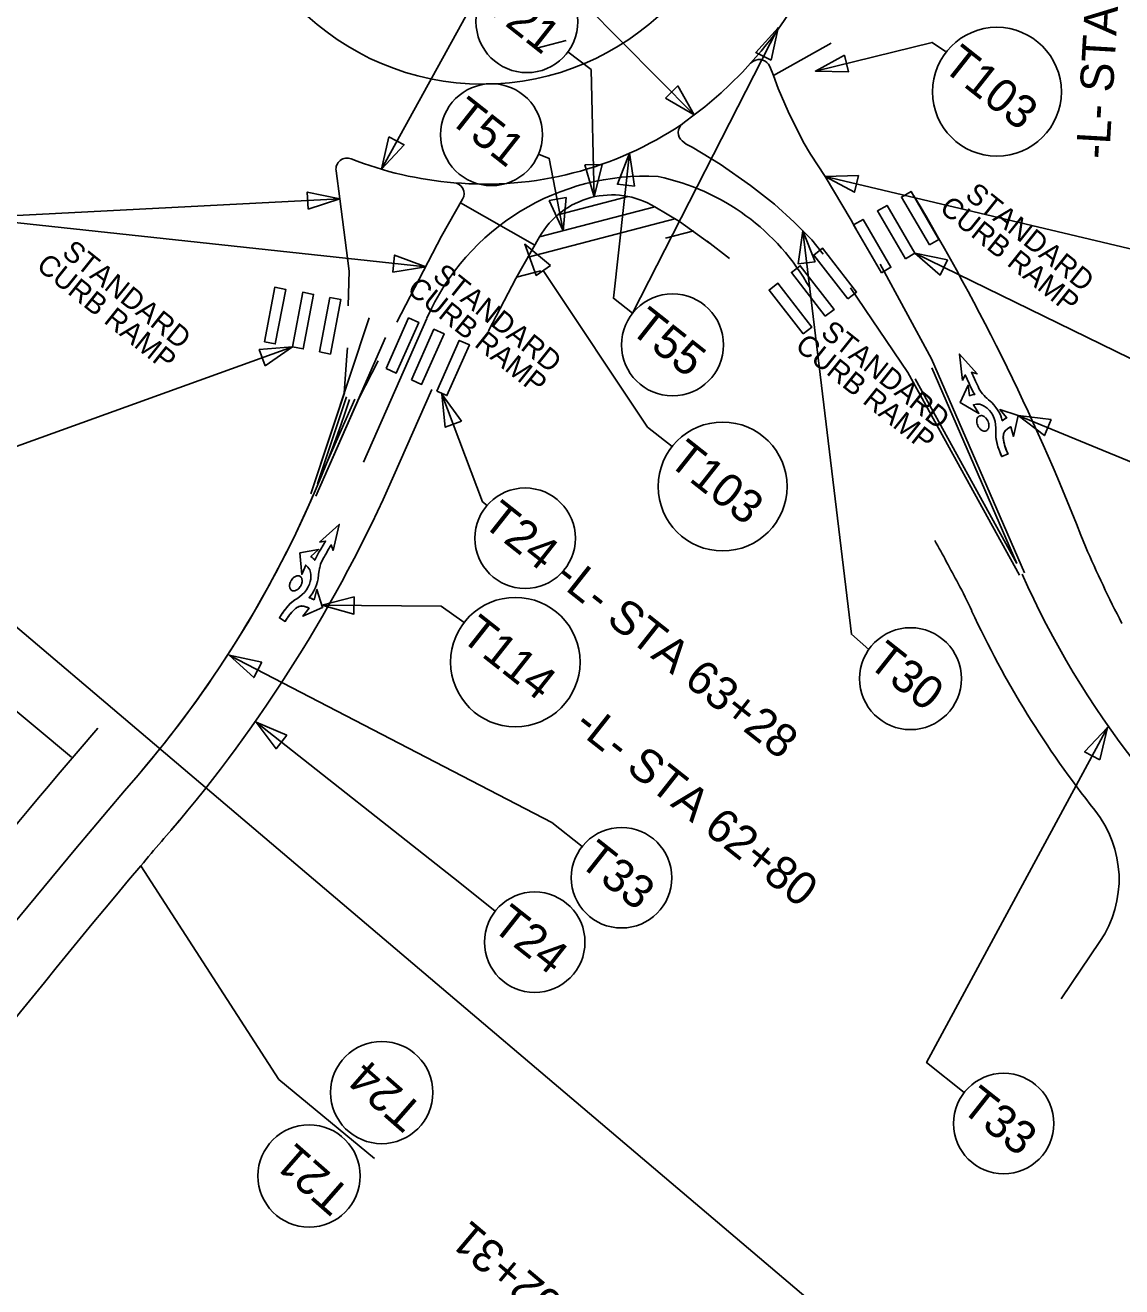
# Model space of a CAD drawing. Extents: x 553958 to 562499, y 493978 to 516388.
# Drawn here: x 557610 to 557807.8, y 506659.2 to 506886.7 of the extents above; entities that cross this region are included whole.
import ezdxf

# ---------------------------------------------------------------- set-up
doc = ezdxf.new("R2010")
doc.units = 0
for name, color, linetype in [('Default', 7, 'Continuous'), ('Exist Horizontal Alignment', 7, 'Continuous'), ('Prop Approach Slab', 7, 'Continuous'), ('Prop Conc 4in Sidewalk', 7, 'Continuous'), ('Prop Conc Curb and Gutter', 7, 'Continuous'), ('Prop EOT', 7, 'Continuous'), ('Prop EOT Dash', 7, 'Continuous'), ('Prop Erosion Rip Rap Class II Label', 7, 'Continuous'), ('Prop Horizontal Alignment Tick Label', 7, 'Continuous'), ('Prop SS Cut Line', 7, 'Continuous'), ('Prop SS Fill Line', 7, 'Continuous'), ('Raster_Level_0', 7, 'Continuous'), ('Scratch_Level_4', 7, 'Continuous'), ('Sheet Plan CELL', 7, 'Continuous'), ('Sheet Plot Border Inside CELL', 7, 'Continuous'), ('Sheet Plot Border Outside CELL', 7, 'Continuous')]:
    doc.layers.add(name, color=color, linetype=linetype)

msp = doc.modelspace()

# ---------------------------------------------------------------- linework, layer by layer
at = {"layer": 'Default'}
msp.add_arc((557478.54, 506881.64), 200, 319.3989, 341.8064, dxfattribs=at)
at = {"layer": 'Exist Horizontal Alignment'}
msp.add_circle((557692.58, 506923.08), 47, dxfattribs=at)
at = {"layer": 'Prop Approach Slab'}
for p, q in [((557618.37, 506754.68), (557488.54, 506863.27)), ((557619.58, 506755.76), (557623.14, 506759.92)), ((557623.01, 506759.77), (557623.02, 506759.77)), ((557630.89, 506735.12), (557655.77, 506696.56)), ((557655.77, 506696.56), (557673.04, 506682.35))]:
    msp.add_line(p, q, dxfattribs=at)
msp.add_lwpolyline([(557687.87, 506911.55), (557697.91, 506903.62), (557730.67, 506870.51)], dxfattribs=at)
msp.add_lwpolyline([(557725.49, 506873.54), (557730.67, 506870.51), (557727.69, 506875.73)], close=True, dxfattribs=at)
for centre in [(557700.51, 506887.33), (557694.12, 506866.95)]:
    msp.add_circle(centre, 9.19, dxfattribs=at)
at = {"layer": 'Prop Conc Curb and Gutter'}
msp.add_line((557671.03, 506807.9), (557682.47, 506833.83), dxfattribs=at)
for centre, radius, start, end in [((557721.81, 506816.48), 43, 86.8578, 156.1909), ((557715.73, 506819.23), 41.05, 29.3788, 78.1467)]:
    msp.add_arc(centre, radius, start, end, dxfattribs=at)
at = {"layer": 'Prop EOT'}
msp.add_line((557676.52, 506805.48), (557683.37, 506821), dxfattribs=at)
for centre, radius, start, end in [((557437.73, 506910.84), 261, 319.5426, 336.1909), ((558769.28, 505775.3), 1511, 139.54257, 142.88486), ((558771.28, 505774.06), 1491.35, 139.437, 139.87766)]:
    msp.add_arc(centre, radius, start, end, dxfattribs=at)
at = {"layer": 'Prop EOT Dash'}
for p, q in [((557661.53, 506802.16), (557672.09, 506833.93)), ((557662.44, 506801.76), (557675.01, 506830.38)), ((557790.23, 506787.92), (557773.46, 506826.53)), ((557789.33, 506787.5), (557769.19, 506824.07))]:
    msp.add_line(p, q, dxfattribs=at)
at = {"layer": 'Prop Erosion Rip Rap Class II Label'}
for points in [[(557425.46, 506933.59), (557889.73, 506539.36), (558124.72, 506519.69), (558557.87, 506177.2), (558959.56, 506684.21), (558454.57, 507154), (558185.43, 507366.81), (557535.46, 507286.55), (557335.3, 506986.11)], [(557510.24, 505740.54), (557854.59, 506431.05), (557889.73, 506539.36), (557425.46, 506933.59), (557046.6, 506628.46), (556899.98, 506318.25), (557006.57, 505850.3)]]:
    msp.add_lwpolyline(points, close=True, dxfattribs=at)
at = {"layer": 'Prop Horizontal Alignment Tick Label'}
msp.add_line((557796.84, 506711.13), (557800.95, 506717.2), dxfattribs=at)
at = {"layer": 'Prop SS Cut Line'}
for centre, radius, start, end in [((557692.71, 506924.09), 65.36, 317.419, 337.4894), ((557692.97, 506921.74), 63.7, 264.9256, 303.9381)]:
    msp.add_arc(centre, radius, start, end, dxfattribs=at)
at = {"layer": 'Prop SS Fill Line'}
for p, q in [((557739.39, 506878.24), (557740.84, 506879.87)), ((557741.38, 506880.2), (557740.84, 506879.87)), ((557737.04, 506875.94), (557739.39, 506878.24)), ((557735.56, 506874.52), (557737.04, 506875.94)), ((557732.61, 506872), (557734.29, 506873.39)), ((557735.56, 506874.52), (557734.29, 506873.39)), ((557728.94, 506869.23), (557730.67, 506870.51)), ((557732.61, 506872), (557730.67, 506870.51)), ((557728.94, 506869.23), (557728.53, 506868.89)), ((557803.83, 506721.46), (557796.84, 506711.13))]:
    msp.add_line(p, q, dxfattribs=at)
for centre, radius, start, end in [((557742.43, 506878.5), 2, 22.2051, 121.6618), ((557729.8, 506867.35), 2, 129.4317, 230.0864), ((557668.07, 506860.73), 2, 68.5384, 187.5292), ((557692.58, 506923.08), 65, 248.5384, 265.3704), ((557687.18, 506856.3), 2, 330.2849, 85.3704), ((557413.43, 506642.2), 415.96, 21.2102, 30.9181), ((557398.44, 506584.5), 429.97, 27.9477, 29.122), ((558043.01, 506898.58), 263.97, 203.6499, 206.9793), ((557689.93, 506739.15), 100, 24.8121, 27.9477), ((557940.45, 506854.97), 176, 204.8121, 218.6034), ((557787.28, 506732.68), 20, 325.8636, 38.6034)]:
    msp.add_arc(centre, radius, start, end, dxfattribs=at)
at = {"layer": 'Raster_Level_0'}
msp.add_line((557627.95, 506748.62), (557630.39, 506751.48), dxfattribs=at)
for centre, radius, start, end in [((557478.54, 506881.64), 200, 319.3989, 336.5223), ((557940.45, 506854.97), 165, 204.0535, 231.806), ((558769.28, 505775.3), 1500, 139.54257, 161.63616)]:
    msp.add_arc(centre, radius, start, end, dxfattribs=at)
at = {"layer": 'Scratch_Level_4'}
for points in [[(557773.07, 506847.07), (557768.03, 506855.71), (557769.76, 506856.71), (557774.8, 506848.07)], [(557768.75, 506844.55), (557763.71, 506853.19), (557765.44, 506854.2), (557770.47, 506845.56)], [(557764.43, 506842.03), (557759.39, 506850.67), (557761.12, 506851.68), (557766.15, 506843.04)], [(557758.36, 506837.34), (557752.24, 506845.25), (557753.82, 506846.48), (557759.94, 506838.57)], [(557754.31, 506834.2), (557748.2, 506842.11), (557749.78, 506843.33), (557755.9, 506835.42)], [(557653.17, 506829.6), (557655.04, 506839.43), (557657.01, 506839.05), (557655.14, 506829.23)], [(557750.3, 506831.02), (557744.18, 506838.93), (557745.76, 506840.16), (557751.88, 506832.25)], [(557658.21, 506828.7), (557660.08, 506838.53), (557662.04, 506838.15), (557660.18, 506828.33)], [(557663.13, 506827.77), (557664.99, 506837.59), (557666.96, 506837.22), (557665.09, 506827.39)], [(557675.11, 506824.76), (557679.17, 506833.9), (557680.99, 506833.09), (557676.94, 506823.95)], [(557679.68, 506822.74), (557683.74, 506831.87), (557685.56, 506831.06), (557681.5, 506821.92)], [(557684.25, 506820.71), (557688.31, 506829.85), (557690.13, 506829.03), (557686.07, 506819.89)]]:
    msp.add_lwpolyline(points, close=True, dxfattribs=at)
at = {"layer": 'Sheet Plan CELL'}
for points in [[(557687.87, 506911.55), (557697.91, 506903.62), (557674.29, 506860.71)], [(557719.55, 506834.74), (557745.8, 506886.22)], [(557707.91, 506881.89), (557712.12, 506878.7), (557712.62, 506855.75)], [(557775.97, 506881.92), (557773.55, 506883.6), (557752.52, 506878.41)], [(557702.61, 506863.41), (557704.54, 506862.66), (557707.03, 506849.63)], [(557719.55, 506834.74), (557716.11, 506837.47), (557719.01, 506863.61)], [(557824.48, 506838.7), (557815.88, 506844.83), (557754.27, 506859.43)], [(557593.34, 506857.45), (557600.29, 506851.96), (557666.76, 506855.36)], [(557593.34, 506857.45), (557600.29, 506851.96), (557682.25, 506843.15)], [(557762.14, 506774.14), (557759.01, 506776.86), (557750.28, 506849.59)], [(557834.46, 506812.15), (557827.3, 506817.81), (557770.47, 506845.56)], [(557726.68, 506810.72), (557722.27, 506814.21), (557703.46, 506842.47)], [(557590.14, 506810.92), (557596.04, 506806.25), (557658.21, 506828.7)], [(557693.32, 506800.11), (557692.52, 506800.77), (557685.18, 506820.15)], [(557864.74, 506781.88), (557856.09, 506788.72), (557789.06, 506816.34)], [(557689.19, 506779), (557685.03, 506781.95), (557663.53, 506782.09)], [(557710.46, 506738.58), (557705.01, 506742.9), (557646.83, 506773.11)], [(557694.8, 506726.96), (557688.39, 506732.03), (557651.69, 506761.04)], [(557779.37, 506694.26), (557772.56, 506699.64), (557805.18, 506760.06)]]:
    msp.add_lwpolyline(points, dxfattribs=at)
for points in [[(557744.52, 506880.36), (557745.8, 506886.22), (557741.76, 506881.79)], [(557757.78, 506881.3), (557752.52, 506878.41), (557758.52, 506878.29)], [(557675.6, 506866.56), (557674.29, 506860.71), (557678.35, 506865.12)], [(557710.95, 506861.51), (557712.62, 506855.75), (557714.05, 506861.57)], [(557719.92, 506857.68), (557719.01, 506863.61), (557716.83, 506858.02)], [(557760.27, 506859.61), (557754.27, 506859.43), (557759.55, 506856.58)], [(557661.05, 506853.51), (557666.76, 506855.36), (557660.89, 506856.61)], [(557704.52, 506855.08), (557707.03, 506849.63), (557707.58, 506855.61)], [(557752.51, 506844.02), (557750.28, 506849.59), (557749.43, 506843.65)], [(557704.73, 506843.36), (557700.11, 506847.19), (557702.2, 506841.57)], [(557776.36, 506844.41), (557770.47, 506845.56), (557775, 506841.62)], [(557676.34, 506842.15), (557682.25, 506843.15), (557676.63, 506845.24)], [(557653.29, 506825.27), (557658.21, 506828.7), (557652.24, 506828.19)], [(557688.69, 506815.28), (557685.18, 506820.15), (557685.78, 506814.18)], [(557795.01, 506815.57), (557789.06, 506816.34), (557793.83, 506812.7)], [(557669.34, 506783.61), (557663.53, 506782.09), (557669.32, 506780.5)], [(557652.69, 506771.82), (557646.83, 506773.11), (557651.26, 506769.06)], [(557657.2, 506758.66), (557651.69, 506761.04), (557655.28, 506756.23)], [(557803.79, 506754.22), (557805.18, 506760.06), (557801.06, 506755.69)]]:
    msp.add_lwpolyline(points, close=True, dxfattribs=at)
for centre, radius in [((557785.25, 506874.69), 11.62), ((557726.76, 506829.04), 9.19), ((557735.8, 506803.51), 11.62), ((557700.18, 506794.18), 9.06), ((557698.42, 506771.85), 11.67), ((557769.67, 506768.86), 9.19), ((557717.57, 506732.96), 9.06), ((557701.91, 506721.34), 9.06), ((557674.33, 506694.23), 9.22), ((557786.47, 506688.64), 9.06), ((557661.23, 506679.19), 9.22)]:
    msp.add_circle(centre, radius, dxfattribs=at)
at = {"layer": 'Sheet Plot Border Inside CELL'}
for p, q in [((557702.05, 506882.49), (557707.59, 506883.93)), ((557744.95, 506877.63), (557755.38, 506883.43)), ((557688.55, 506854.67), (557701.93, 506847.02)), ((557718.77, 506855.8), (557706.06, 506852.48)), ((557723.55, 506853.95), (557702.79, 506848.53)), ((557723.55, 506853.95), (557728.01, 506851.27)), ((557727.15, 506851.79), (557700.71, 506844.88)), ((557728.01, 506851.27), (557733.45, 506847.4)), ((557702.79, 506848.53), (557698.51, 506841.02)), ((557730.63, 506849.6), (557725.52, 506848.26)), ((557733.01, 506847.75), (557737.02, 506844.63)), ((557698.51, 506841.02), (557693.59, 506831.57)), ((557703.03, 506842.39), (557698.62, 506841.24))]:
    msp.add_line(p, q, dxfattribs=at)
for points in [[(557779.06, 506822.64), (557778.5, 506827.4), (557781.67, 506823.8), (557780.68, 506824.1), (557781.2, 506822.92), (557781.38, 506822.52), (557781.57, 506822.13), (557781.67, 506821.9), (557781.86, 506821.52), (557782.02, 506821.2), (557782.19, 506820.89), (557782.44, 506820.52), (557782.65, 506820.25), (557782.82, 506820.05), (557782.96, 506819.9), (557783.22, 506819.64), (557783.43, 506819.44), (557783.76, 506819.16), (557784.31, 506818.66), (557784.68, 506818.26), (557785.08, 506817.77), (557785.37, 506817.35), (557785.7, 506816.77), (557785.94, 506816.24), (557786.08, 506815.85), (557786.21, 506815.38), (557786.45, 506815.55), (557786.76, 506815.75), (557787.02, 506815.9), (557785.78, 506817.38), (557789.06, 506816.34), (557788.26, 506812.53), (557787.76, 506814.29), (557787.41, 506814.08), (557787.23, 506813.96), (557787.08, 506813.86), (557786.94, 506813.74), (557786.82, 506813.62), (557786.65, 506813.41), (557786.57, 506813.28), (557786.48, 506813.02), (557786.44, 506812.88), (557786.41, 506812.69), (557786.39, 506812.46), (557786.4, 506812.22), (557786.43, 506812.04), (557786.48, 506811.68), (557786.55, 506811.36), (557786.63, 506811.03), (557786.73, 506810.67), (557786.83, 506810.38), (557786.97, 506810.01), (557787.11, 506809.69), (557787.25, 506809.4), (557786.13, 506808.9), (557785.98, 506809.25), (557785.7, 506809.96), (557785.44, 506810.68), (557785.23, 506811.43), (557785.13, 506811.97), (557785.07, 506812.57), (557785.06, 506813.02), (557785.08, 506813.43), (557785.07, 506814.05), (557785.02, 506814.67), (557784.93, 506815.23), (557784.77, 506815.79), (557784.5, 506816.37), (557784.22, 506816.83), (557783.92, 506817.21), (557783.62, 506817.54), (557783.48, 506817.63), (557782.96, 506818.01), (557782.61, 506818.2), (557782.16, 506818.34), (557781.84, 506818.38), (557781.56, 506818.35), (557781.02, 506818.24), (557782, 506816.69), (557778.63, 506818.63), (557780.04, 506821.77), (557780.31, 506819.87), (557780.6, 506819.98), (557780.84, 506820.04), (557781.12, 506820.08), (557781.25, 506820.08), (557780.98, 506820.54), (557780.71, 506821.05), (557780.49, 506821.51), (557780.23, 506822.09), (557779.53, 506823.64)], [(557663.1, 506793.48), (557666.68, 506796.66), (557665.55, 506792), (557665.23, 506792.98), (557664.56, 506791.88), (557664.34, 506791.5), (557664.12, 506791.13), (557664, 506790.91), (557663.79, 506790.54), (557663.62, 506790.22), (557663.47, 506789.91), (557663.31, 506789.5), (557663.2, 506789.17), (557663.14, 506788.91), (557663.09, 506788.71), (557663.03, 506788.35), (557662.98, 506788.06), (557662.94, 506787.63), (557662.85, 506786.89), (557662.73, 506786.36), (557662.56, 506785.75), (557662.38, 506785.27), (557662.1, 506784.67), (557661.8, 506784.17), (557661.56, 506783.83), (557661.24, 506783.45), (557661.52, 506783.36), (557661.86, 506783.22), (557662.14, 506783.09), (557662.64, 506784.95), (557663.67, 506781.67), (557660.08, 506780.15), (557661.24, 506781.56), (557660.87, 506781.73), (557660.67, 506781.81), (557660.49, 506781.87), (557660.31, 506781.92), (557660.15, 506781.95), (557659.88, 506781.97), (557659.73, 506781.95), (557659.46, 506781.89), (557659.32, 506781.84), (557659.15, 506781.76), (557658.96, 506781.64), (557658.77, 506781.49), (557658.63, 506781.37), (557658.37, 506781.12), (557658.14, 506780.88), (557657.91, 506780.62), (557657.68, 506780.34), (557657.5, 506780.09), (557657.28, 506779.76), (557657.09, 506779.46), (557656.94, 506779.18), (557655.88, 506779.82), (557656.09, 506780.13), (557656.51, 506780.77), (557656.95, 506781.39), (557657.45, 506782), (557657.83, 506782.39), (557658.29, 506782.79), (557658.66, 506783.05), (557659, 506783.27), (557659.51, 506783.63), (557659.99, 506784.03), (557660.39, 506784.42), (557660.75, 506784.87), (557661.08, 506785.43), (557661.3, 506785.92), (557661.44, 506786.38), (557661.54, 506786.82), (557661.53, 506786.98), (557661.54, 506787.63), (557661.5, 506788.02), (557661.36, 506788.48), (557661.2, 506788.75), (557661.02, 506788.97), (557660.62, 506789.35), (557659.91, 506787.66), (557659.57, 506791.53), (557662.95, 506792.17), (557661.55, 506790.86), (557661.81, 506790.69), (557661.99, 506790.52), (557662.18, 506790.32), (557662.26, 506790.22), (557662.49, 506790.7), (557662.75, 506791.21), (557663, 506791.66), (557663.33, 506792.2), (557664.2, 506793.66)]]:
    msp.add_lwpolyline(points, close=True, dxfattribs=at)
for points in [[(557787.76, 506814.29), (557788.26, 506812.53), (557789.06, 506816.34), (557785.78, 506817.38), (557787.02, 506815.9)], [(557786.13, 506808.9), (557787.25, 506809.4)], [(557661.24, 506781.56), (557660.08, 506780.15), (557663.67, 506781.67), (557662.64, 506784.95), (557662.14, 506783.09)], [(557655.88, 506779.82), (557656.94, 506779.18)]]:
    msp.add_lwpolyline(points, dxfattribs=at)
for centre, radius, start, end in [((557715.82, 506841.09), 15, 58.9904, 150.2849), ((557782.44, 506815.53), 0.777, 138.4443, 158.6453), ((557782.42, 506815.56), 0.742, 115.3307, 138.4443), ((557782.36, 506815.67), 0.613, 114.0973, 115.3307), ((557782.36, 506815.67), 0.613, 112.8639, 114.0973), ((557782.41, 506815.55), 0.742, 89.7503, 112.8639), ((557782.41, 506815.52), 0.777, 69.5494, 89.7503), ((557782.19, 506814.94), 1.4, 46.8199, 69.5494), ((557781.78, 506814.49), 2.01, 38.835, 46.8199), ((557789.72, 506810.86), 5.72, 118.1402, 127.8449), ((557783.02, 506815.31), 1.4, 158.6453, 181.3747), ((557783.63, 506815.32), 2.01, 181.3747, 189.3596), ((557783.73, 506815.34), 2.1, 189.3596, 202.0588), ((557783.61, 506815.29), 1.98, 202.0588, 204.0973), ((557783.61, 506815.29), 1.98, 204.0973, 206.1359), ((557783.72, 506815.35), 2.1, 206.1359, 218.835), ((557783.65, 506815.29), 2.01, 218.835, 226.8199), ((557783.23, 506814.84), 1.4, 226.8199, 249.5494), ((557783.01, 506814.22), 0.742, 295.3307, 318.4443), ((557781.7, 506814.43), 2.1, 26.1359, 38.835), ((557782.98, 506814.24), 0.777, 318.4443, 338.6453), ((557781.81, 506814.49), 1.98, 24.0973, 26.1359), ((557781.81, 506814.49), 1.98, 22.0588, 24.0973), ((557781.7, 506814.44), 2.1, 9.3596, 22.0588), ((557782.4, 506814.47), 1.4, 338.6453, 1.3747), ((557781.79, 506814.46), 2.01, 1.3747, 9.3596), ((557788.24, 506812.31), 1.93, 123.5814, 146.6734), ((557790.09, 506809.9), 4.97, 117.9747, 126.0157), ((557783.01, 506814.26), 0.777, 249.5494, 269.7503), ((557783.01, 506814.22), 0.742, 269.7503, 292.8639), ((557783.06, 506814.1), 0.613, 292.8639, 294.0973), ((557783.06, 506814.1), 0.613, 294.0973, 295.3307), ((557772.2, 506813.86), 12.88, 355.8069, 358.1063), ((557792.26, 506813.02), 7.21, 180.8414, 198.8402), ((557788.47, 506812.44), 2.07, 168.0136, 186.2206), ((557794.58, 506813.14), 8.23, 186.4124, 207.0071), ((557788.27, 506812.47), 1.88, 151.3474, 167.4973), ((557806.97, 506817.93), 22.71, 198.5786, 203.4377), ((557659.79, 506785.48), 2.1, 151.049, 163.7481), ((557659.69, 506785.54), 1.98, 149.0104, 151.049), ((557659.69, 506785.54), 1.98, 146.9719, 149.0104), ((557659.79, 506785.47), 2.1, 134.2727, 146.9719), ((557659.72, 506785.54), 2.01, 126.2878, 134.2727), ((557659.36, 506786.03), 1.4, 103.5584, 126.2878), ((557659.22, 506786.63), 0.777, 83.3574, 103.5584), ((557659.22, 506786.67), 0.742, 60.2438, 83.3574), ((557659.28, 506786.78), 0.613, 59.0104, 60.2438), ((557659.28, 506786.78), 0.613, 57.777, 59.0104), ((557659.22, 506786.67), 0.742, 34.6634, 57.777), ((557659.19, 506786.65), 0.777, 14.4625, 34.6634), ((557657.98, 506786.59), 2.01, 343.7481, 351.733), ((557658.58, 506786.5), 1.4, 351.733, 14.4625), ((557659.1, 506785.59), 1.4, 171.733, 194.4625), ((557659.7, 506785.5), 2.01, 163.7481, 171.733), ((557658.5, 506785.44), 0.777, 194.4625, 214.6634), ((557658.47, 506785.42), 0.742, 214.6634, 237.777), ((557658.4, 506785.31), 0.613, 237.777, 239.0104), ((557658.4, 506785.31), 0.613, 239.0104, 240.2438), ((557658.46, 506785.42), 0.742, 240.2438, 263.3574), ((557658.47, 506785.45), 0.777, 263.3574, 283.5584), ((557658.32, 506786.06), 1.4, 283.5584, 306.2878), ((557657.96, 506786.55), 2.01, 306.2878, 314.2727), ((557657.89, 506786.62), 2.1, 314.2727, 326.9719), ((557658, 506786.55), 1.98, 326.9719, 329.0104), ((557658, 506786.55), 1.98, 329.0104, 331.049), ((557657.89, 506786.61), 2.1, 331.049, 343.7481), ((557662.78, 506777.15), 7.21, 125.7545, 143.7533), ((557651.98, 506794.07), 12.88, 300.72, 303.0194), ((557660.13, 506779.93), 2.07, 112.9267, 131.1337), ((557660.04, 506780.11), 1.88, 96.2605, 112.4104), ((557659.89, 506780.03), 1.93, 68.4945, 91.5865), ((557658.97, 506777.13), 4.97, 62.8878, 70.9288), ((557659.55, 506777.99), 5.72, 63.0534, 72.758), ((557675.22, 506767.9), 22.71, 143.4917, 148.3508), ((557664.2, 506775.31), 8.23, 131.3255, 151.9202), ((558771.28, 505774.06), 1491.35, 139.87766, 148.26076)]:
    msp.add_arc(centre, radius, start, end, dxfattribs=at)
at = {"layer": 'Sheet Plot Border Outside CELL'}
for p, q in [((557744.96, 506877.61), (557744.28, 506879.26)), ((557745.8, 506875.29), (557744.96, 506877.61)), ((557747.62, 506871.16), (557745.8, 506875.29)), ((557750.34, 506865.69), (557747.62, 506871.16)), ((557728.52, 506865.82), (557729.22, 506865.23)), ((557729.22, 506865.23), (557730.28, 506864.7)), ((557730.28, 506864.7), (557735.38, 506861.65)), ((557751.65, 506863.44), (557750.34, 506865.69)), ((557735.38, 506861.65), (557740.82, 506857.78)), ((557754.27, 506859.43), (557751.65, 506863.44)), ((557666.76, 506855.36), (557666.09, 506860.46)), ((557759, 506851.53), (557754.27, 506859.43)), ((557740.82, 506857.78), (557745.16, 506854.41)), ((557668.43, 506842.36), (557666.76, 506855.36)), ((557685.12, 506848.67), (557688.91, 506855.31)), ((557745.16, 506854.41), (557748.68, 506851.18)), ((557748.68, 506851.18), (557751.88, 506847.99)), ((557759.98, 506849.7), (557759, 506851.53)), ((557677.05, 506833.14), (557685.13, 506848.67)), ((557751.88, 506847.99), (557753.91, 506845.42)), ((557764.21, 506843.63), (557773.46, 506826.53)), ((557668.26, 506836.07), (557668.43, 506842.38)), ((557769.2, 506824.05), (557758.86, 506839.32)), ((557668.02, 506827.13), (557668.15, 506828.49)), ((557667.58, 506820.32), (557668.02, 506827.12)), ((557673.69, 506826.15), (557670.23, 506819.49)), ((557790.23, 506787.92), (557773.46, 506826.53)), ((557789.32, 506787.51), (557769.19, 506824.07)), ((557788.83, 506789.65), (557770.51, 506822.92)), ((557788.83, 506789.65), (557773.52, 506824.88)), ((557661.53, 506802.16), (557667.59, 506820.39)), ((557662.44, 506801.76), (557670.23, 506819.51)), ((557662.77, 506804), (557667.98, 506819.67)), ((557662.77, 506804), (557669.46, 506819.25))]:
    msp.add_line(p, q, dxfattribs=at)

# ---------------------------------------------------------------- texts
at = {"layer": 'Prop Approach Slab'}
for s, p in [('T21', (557692.52, 506889.82)), ('T51', (557686.14, 506869.43))]:
    msp.add_text(s, height=6, rotation=321.6667, dxfattribs=at).set_placement(p)
at = {"layer": 'Prop Conc 4in Sidewalk'}
for s, p in [('STANDARD ', (557779.31, 506855.67)), ('CURB RAMP', (557774.69, 506853.28)), ('STANDARD ', (557616.46, 506845.31)), ('CURB RAMP', (557611.84, 506842.92)), ('STANDARD ', (557683.29, 506841.06)), ('CURB RAMP', (557678.67, 506838.67)), ('STANDARD ', (557753.27, 506830.83)), ('CURB RAMP', (557748.65, 506828.44))]:
    msp.add_text(s, height=3.75, rotation=321.3322, dxfattribs=at).set_placement(p)
at = {"layer": 'Sheet Plan CELL'}
for s, rotation, p in [('-L- STA ', 86.6749, (557805.48, 506862.47)), ('T103', 321.6667, (557775.16, 506878.85)), ('T55', 321.6667, (557718.78, 506831.53)), ('T103', 321.6667, (557725.7, 506807.67)), ('T24', 321.6667, (557692.2, 506796.67)), ('-L- STA 63+28', 321.6667, (557705.16, 506786.6)), ('T114', 321.6667, (557688.29, 506776.04)), ('T30', 321.6667, (557761.7, 506771.34)), ('-L- STA 62+80', 321.6667, (557708.72, 506759.89)), ('T33', 321.6667, (557709.59, 506735.44)), ('T24', 321.6667, (557693.93, 506723.82)), ('T24', 138.8115, (557682.19, 506691.33)), ('T33', 321.6667, (557778.5, 506691.12)), ('T21', 138.8115, (557669.09, 506676.29)), ('-L- STA 62+31', 139.8645, (557730.32, 506637.6))]:
    msp.add_text(s, height=6, rotation=rotation, dxfattribs=at).set_placement(p)

doc.saveas('drawing.dxf')
